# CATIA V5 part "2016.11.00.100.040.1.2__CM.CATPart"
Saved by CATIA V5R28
Part number: 2016.11.00.100.040.1.2__CM
Property "id_number": "2016.11.00.100.040.1.2"
Publications: "Absolute Axis System", "driver", "slider", "base", "cam diagram"
Bounding box of the stored display mesh (mm): x -40 to 190, y -87.5 to 87.5, z 0 to 240
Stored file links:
  N:\B2\Normteile\K\2016\11-14\010\cm\2016.11.00.100.040.1.2__CM.CATPart
  H:\CAD_Startmodelle\Tests\fill-in_PRT-SL_TEMPLATE.xlsx
  H:\CAD_Startmodelle\V5-R24\R24_TEMPLATE_PRT_FIBRO_CAM_TECNOLOGIES_INDEX.xlsx
  H:\z_Einordnen\170511__Anfrage_TK_HN\170511__CC01_TKHN.CATPart
  N:\B2\Normteile\K\2016\9xxx\2016.9024.1705.001\Entwurf_\170511__CC01_TKHN.CATPart
  N:\B2\Normteile\K\2016\9xxx\2016.9024.1707.006\Konstruktion\2016.9024.1707.006__HP__CUSTOMIZED_CAM_CM.CATPart
  N:\B2\Normteile\K\2016\9xxx\2016.9024.1707.005\Konstruktion\2016.9024.1707.005__HP__CUSTOMIZED_CAM_CM.CATPart
  N:\B2\Normteile\K\2016\9xxx\2016.9024.1707.008\Konstruktion\2016.9024.1707.008__HP__CUSTOMIZED_CAM_CM.CATPart
  N:\B2\Normteile\K\2016\9xxx\2016.9024.1707.009\Konstruktion\2016.9024.1707.009__HP__CUSTOMIZED_CAM_CM.CATPart
  N:\B2\Normteile\K\2016\9xxx\2016.9024.1707.010\Konstruktion\2016.9024.1707.010__HP__CUSTOMIZED_CAM_CM.CATPart
  N:\B2\Normteile\K\2016\9xxx\2016.9024.1708.002\Konstruktion\2016.9024.1708.002__HP__CUSTOMIZED_CAM_CM.CATPart
  N:\B2\Normteile\K\2016\9xxx\2016.9024.1802.001\Konstruktion\2016.9024.1802.001__HP__CUSTOMIZED_CAM_CM.CATPart
  N:\B2\Normteile\K\2016\9xxx\2016.9024.1802.002\Konstruktion\2016.9024.1802.002__HP__CUSTOMIZED_CAM_CM.CATPart
  N:\B2\Normteile\K\2016\9xxx\2016.9024.1811.003\Konstruktion\2016.9024.1811.003__HP__CUSTOMIZED_CAM_CM.CATPart
  N:\B2\Normteile\K\2016\9xxx\2016.9015.1811.001\Konstruktion\am\2016.9015.1811.001__AM__FCC_HV_DMC_0125-00.CATPart
  N:\B2\Normteile\K\2016\9xxx\2016.9024.1811.009\Konstruktion\2016.9024.1811.009__HP__CUSTOMIZED_CAM_CM.CATPart
  N:\B2\Normteile\K\2016\9xxx\2016.9024.1911.002\Konstruktion\am\2016.9024.1911.002__AM__CUSTOMIZED_CAM_CM.CATPart
  N:\B2\Normteile\K\2016\9xxx\2016.9024.2002.006\Konstruktion\2016.9024.2002.006__AM.CATPart
  N:\B2\Normteile\K\2016\9xxx\2016.9024.2004.001\Konstruktion\2016.9024.2004.001__AM__FCC_HV_CAEC_0260-45.CATPart
  N:\B2\Normteile\K\2016\9xxx\2016.9024.2006.002\Konstruktion\2016.9024.2006.002__AM__FCC_HV_CAEC_0260-40.CATPart
  N:\B2\Normteile\K\2016\9xxx\2016.9024.2006.005\Konstruktion\am\2016.9024.2006.005__AM__CFCC_HV_AEPC_0080-65.CATPart
  N:\B2\Normteile\K\2016\9xxx\2016.9024.2006.004\Konstruktion\am\2016.9024.2006.004__AM__CFCC_HV_AEC_0210-35.CATPart
  N:\B2\Normteile\K\2016\9xxx\2016.9026.2006.001\Konstruktion\am\2016.9026.2006.001__AM__FCC_LV_CAEC_0180-40.CATPart
  N:\B2\Normteile\K\2016\9xxx\2016.9015.2007.001\Konstruktion\am\2016.9015.2007.001__AM__FCC_HV_CDMPC_0090-00.CATPart
  N:\B2\Normteile\K\2016\9xxx\2016.9024.2005.001\Konstruktion\am\2016.9024.2005.001__AM__CFCC_HV_AEPC_1400-70.CATPart
  N:\B2\Normteile\K\2016\9xxx\2016.9024.2007.004\Konstruktion\am\2016.9024.2007.004__AM__CFCC_HV_AEC_1250-80.CATPart
  N:\B2\Normteile\K\2016\11-14\005\2016.11.00.052.040.1.02__AS__DIE_MOUNT_CAM__W52_A0_S40.CATProduct
  N:\B2\Normteile\K\2016\11-14\cm\005\catia\2016.11.00.052.025.1.2__CM.CATPart
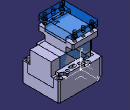
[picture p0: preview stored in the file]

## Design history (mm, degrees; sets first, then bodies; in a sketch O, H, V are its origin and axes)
Parameters
  group "process_parameters"
    modeltype = ""
    stocklist = ""
    id_number = "2016.11.00.100.040.1.2"
    id_number_rough_part = ""
    revision_index = ""
    revision_date = ""
    revision_description = ""
    category = ""
    material = ""
    manufacturing_information = ""
    standard = ""
  group "release_parameters_startmodel"
    sm_revision_index = "2016_00" {design table}
    sm_revision_date = "20.08.2016" {design table}
    sm_revision_name = "Meyer" {design table}
    sm_revision_description = "new part template FIBRO cam tecnologies" {design table}
AxisSystem1: origin (0, 0, 0), X (1, 0, 0), Y (0, 1, 0), Z (0, 0, 1)
Set1 "reference elements"
  Sketch1 "cam diagram" on ZX plane of AxisSystem1, origin (0, 0, 0), H (-1, 0, 0), V (0, 0, 1)
    line L1 (0, 0) -> (40, 0)
    line L2 (40, 0) -> (0, 40)
    point P2 (0, 40)
    line L3 (0, 40) -> (0, 0)
    length L1 = 40
    angle H L2 = 45
    horizontal: L1 H
    coincidence: P2 V
    vertical: L3 V
Body1 "finished_part" (main body)
  Body2 "rough_part"
  Add1 "rough_part": tool Body2
  Body3 "milling operations"
  Remove1 "milling operations": tool Body3
  Body4 "drilling operations"
  Remove2 "drilling operations": tool Body4
Body5 "driver"
  Solid1: solid without history
Body6 "slider"
  Solid2: solid without history
Body7 "base"
  Solid3: solid without history
Body8 "opened position"
  Body9 "slider"
    Body10 "slider"
      Solid4: linked copy from another document
    Assemble1: tool Body10
    Translate1: FirstPoint vertex [element of Sketch1 | element of Sketch1], SecondPoint vertex [element of Sketch1 | element of Sketch1], ToTransfor Assemble1
  Assemble2: tool Body9
  Body11 "driver"
    Body12 "driver"
      Solid5: linked copy from another document
    Assemble3: tool Body12
    Translate2: FirstPoint vertex [element of Sketch1 | element of Sketch1], SecondPoint vertex [element of Sketch1 | element of Sketch1], ToTransfor Assemble3
  Assemble4: tool Body11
